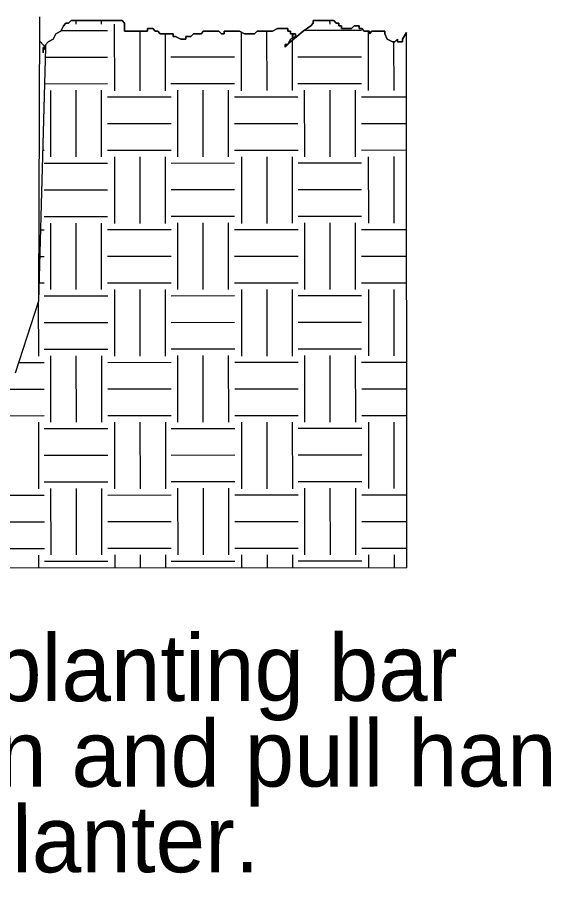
# Model space of a CAD drawing. Extents: x 816132 to 817815, y 885694 to 886789.
# Drawn here: x 816662 to 816715.4, y 886354.3 to 886442.4 of the extents above; entities that cross this region are included whole.
import ezdxf

# ---------------------------------------------------------------- set-up
doc = ezdxf.new("R2010")
doc.units = 0
doc.layers.add('Silt Fence Coir Fiber Wattle Break Detail CELL', color=7, linetype='Continuous')

msp = doc.modelspace()

# ---------------------------------------------------------------- linework, layer by layer
at = {"layer": 'Silt Fence Coir Fiber Wattle Break Detail CELL'}
for p, q in [((816664.16, 886442.456), (816664.068, 886413.823)), ((816667.818, 886442.08), (816667.818, 886441.711)), ((816670.374, 886442.082), (816670.374, 886441.713)), ((816671.7, 886441.714), (816671.705, 886435.01)), ((816693.382, 886442.1), (816693.383, 886441.731)), ((816666.366, 886441.086), (816671.014, 886441.09)), ((816674.257, 886441.006), (816674.261, 886435.012)), ((816676.814, 886440.739), (816676.818, 886435.014)), ((816684.483, 886440.913), (816684.487, 886435.02)), ((816687.039, 886441.016), (816687.044, 886435.022)), ((816689.596, 886440.749), (816689.597, 886440.3)), ((816690.831, 886441.105), (816696.579, 886441.11)), ((816697.265, 886441.024), (816697.27, 886435.03)), ((816701.141, 886387.011), (816701.103, 886440.893)), ((816664.224, 886439.97), (816664.785, 886439.382)), ((816689.596, 886440.084), (816689.6, 886435.024)), ((816699.823, 886439.949), (816699.826, 886435.032)), ((816664.785, 886439.382), (816664.068, 886413.823)), ((816664.757, 886438.404), (816671.016, 886438.408)), ((816677.407, 886438.413), (816683.798, 886438.418)), ((816690.19, 886438.423), (816696.58, 886438.428)), ((816664.682, 886435.722), (816671.018, 886435.727)), ((816677.409, 886435.732), (816683.8, 886435.736)), ((816690.191, 886435.741), (816696.582, 886435.746)), ((816665.267, 886435.051), (816665.271, 886428.347)), ((816667.822, 886435.054), (816667.828, 886428.349)), ((816670.379, 886435.056), (816670.385, 886428.352)), ((816671.019, 886434.386), (816677.41, 886434.391)), ((816678.048, 886435.062), (816678.053, 886428.357)), ((816680.605, 886435.064), (816680.61, 886428.36)), ((816683.161, 886435.066), (816683.166, 886428.362)), ((816683.801, 886434.396), (816690.193, 886434.401)), ((816690.831, 886435.072), (816690.836, 886428.368)), ((816693.387, 886435.074), (816693.392, 886428.37)), ((816695.944, 886435.075), (816695.949, 886428.372)), ((816696.583, 886434.406), (816701.108, 886434.409)), ((816683.804, 886431.714), (816690.194, 886431.719)), ((816696.585, 886431.724), (816701.11, 886431.727)), ((816664.57, 886431.699), (816664.629, 886431.699)), ((816671.021, 886431.704), (816677.412, 886431.709)), ((816664.495, 886429.017), (816664.632, 886429.018)), ((816671.023, 886429.023), (816677.414, 886429.028)), ((816671.709, 886428.353), (816671.715, 886421.649)), ((816674.266, 886428.355), (816674.271, 886421.65)), ((816676.822, 886428.357), (816676.828, 886421.652)), ((816683.805, 886429.033), (816690.196, 886429.038)), ((816684.492, 886428.363), (816684.496, 886421.659)), ((816687.048, 886428.365), (816687.053, 886421.66)), ((816689.605, 886428.367), (816689.61, 886421.663)), ((816696.588, 886429.042), (816701.111, 886429.046)), ((816697.274, 886428.373), (816697.279, 886421.668)), ((816699.831, 886428.375), (816699.836, 886421.671)), ((816664.633, 886427.724), (816671.023, 886427.729)), ((816677.415, 886427.734), (816683.806, 886427.739)), ((816690.197, 886427.743), (816696.588, 886427.749)), ((816664.634, 886425.042), (816671.026, 886425.047)), ((816677.417, 886425.052), (816683.807, 886425.057)), ((816690.199, 886425.062), (816696.59, 886425.067)), ((816664.637, 886422.36), (816671.028, 886422.365)), ((816677.418, 886422.371), (816683.81, 886422.375)), ((816690.201, 886422.38), (816696.592, 886422.385)), ((816665.276, 886421.69), (816665.281, 886414.986)), ((816667.833, 886421.693), (816667.837, 886414.988)), ((816670.389, 886421.694), (816670.394, 886414.99)), ((816678.058, 886421.701), (816678.063, 886414.996)), ((816680.614, 886421.703), (816680.619, 886414.998)), ((816683.171, 886421.705), (816683.176, 886415.001)), ((816690.84, 886421.711), (816690.845, 886415.006)), ((816693.397, 886421.713), (816693.402, 886415.009)), ((816695.953, 886421.714), (816695.958, 886415.011)), ((816664.27, 886421.019), (816664.637, 886421.019)), ((816671.029, 886421.024), (816677.419, 886421.029)), ((816683.811, 886421.035), (816690.202, 886421.04)), ((816696.593, 886421.045), (816701.117, 886421.048)), ((816664.194, 886418.338), (816664.639, 886418.338)), ((816671.03, 886418.342), (816677.421, 886418.348)), ((816683.813, 886418.353), (816690.204, 886418.358)), ((816696.595, 886418.363), (816701.119, 886418.366)), ((816664.12, 886415.656), (816664.641, 886415.656)), ((816671.032, 886415.661), (816677.423, 886415.667)), ((816671.72, 886414.991), (816671.724, 886408.288)), ((816674.276, 886414.993), (816674.281, 886408.289)), ((816676.832, 886414.996), (816676.837, 886408.291)), ((816683.815, 886415.672), (816690.206, 886415.677)), ((816684.501, 886415.001), (816684.506, 886408.298)), ((816687.058, 886415.004), (816687.062, 886408.299)), ((816689.614, 886415.006), (816689.619, 886408.301)), ((816696.597, 886415.681), (816701.121, 886415.685)), ((816697.284, 886415.012), (816697.288, 886408.307)), ((816699.84, 886415.014), (816699.845, 886408.309)), ((816664.642, 886414.362), (816671.034, 886414.368)), ((816677.424, 886414.373), (816683.815, 886414.378)), ((816690.207, 886414.382), (816696.598, 886414.387)), ((816664.068, 886413.823), (816661.727, 886406.589)), ((816664.068, 886413.823), (816661.727, 886406.589)), ((816664.051, 886413.767), (816664.055, 886408.281)), ((816664.643, 886411.68), (816671.035, 886411.686)), ((816677.426, 886411.691), (816683.818, 886411.696)), ((816690.209, 886411.701), (816696.599, 886411.706)), ((816664.646, 886408.999), (816671.037, 886409.004)), ((816677.428, 886409.009), (816683.819, 886409.014)), ((816690.21, 886409.019), (816696.602, 886409.024)), ((816665.286, 886408.329), (816665.29, 886401.625)), ((816667.842, 886408.331), (816667.847, 886401.627)), ((816670.399, 886408.333), (816670.403, 886401.629)), ((816678.067, 886408.339), (816678.073, 886401.635)), ((816680.624, 886408.342), (816680.629, 886401.637)), ((816683.18, 886408.344), (816683.186, 886401.639)), ((816690.85, 886408.35), (816690.854, 886401.645)), ((816693.406, 886408.352), (816693.411, 886401.647)), ((816695.963, 886408.353), (816695.968, 886401.65)), ((816662.072, 886407.657), (816664.647, 886407.658)), ((816671.038, 886407.663), (816677.429, 886407.668)), ((816683.82, 886407.673), (816690.212, 886407.679)), ((816696.602, 886407.684), (816701.127, 886407.687)), ((816658.257, 886404.972), (816664.649, 886404.976)), ((816671.04, 886404.981), (816677.431, 886404.986)), ((816683.822, 886404.991), (816690.213, 886404.997)), ((816696.605, 886405.002), (816701.129, 886405.005)), ((816658.259, 886402.29), (816664.651, 886402.295)), ((816671.042, 886402.3), (816677.433, 886402.305)), ((816683.824, 886402.31), (816690.215, 886402.316)), ((816696.607, 886402.32), (816701.13, 886402.324)), ((816664.06, 886401.624), (816664.064, 886394.92)), ((816664.651, 886401.001), (816671.043, 886401.006)), ((816671.729, 886401.63), (816671.734, 886394.926)), ((816674.286, 886401.632), (816674.29, 886394.928)), ((816676.842, 886401.634), (816676.847, 886394.93)), ((816677.434, 886401.011), (816683.825, 886401.017)), ((816684.511, 886401.64), (816684.516, 886394.936)), ((816687.067, 886401.642), (816687.073, 886394.938)), ((816689.624, 886401.645), (816689.629, 886394.94)), ((816690.216, 886401.021), (816696.607, 886401.026)), ((816697.293, 886401.65), (816697.298, 886394.946)), ((816699.85, 886401.653), (816699.854, 886394.948)), ((816664.654, 886398.319), (816671.045, 886398.324)), ((816677.436, 886398.33), (816683.827, 886398.335)), ((816690.218, 886398.34), (816696.609, 886398.345)), ((816664.656, 886395.637), (816671.046, 886395.643)), ((816677.438, 886395.648), (816683.829, 886395.653)), ((816690.22, 886395.658), (816696.611, 886395.663)), ((816665.295, 886394.968), (816665.3, 886388.264)), ((816667.852, 886394.97), (816667.856, 886388.266)), ((816670.408, 886394.972), (816670.413, 886388.268)), ((816678.078, 886394.978), (816678.082, 886388.274)), ((816680.634, 886394.98), (816680.639, 886388.276)), ((816683.191, 886394.982), (816683.195, 886388.278)), ((816690.859, 886394.988), (816690.865, 886388.284)), ((816693.416, 886394.99), (816693.42, 886388.286)), ((816695.972, 886394.992), (816695.977, 886388.288)), ((816658.265, 886394.292), (816664.656, 886394.297)), ((816671.048, 886394.302), (816677.438, 886394.307)), ((816683.83, 886394.312), (816690.221, 886394.317)), ((816696.612, 886394.322), (816701.136, 886394.326)), ((816658.267, 886391.611), (816664.659, 886391.615)), ((816671.049, 886391.62), (816677.44, 886391.625)), ((816683.832, 886391.63), (816690.223, 886391.635)), ((816696.614, 886391.64), (816701.138, 886391.644)), ((816658.269, 886388.929), (816664.66, 886388.934)), ((816671.051, 886388.939), (816677.443, 886388.944)), ((816683.834, 886388.949), (816690.224, 886388.954)), ((816696.616, 886388.959), (816701.14, 886388.963)), ((816664.069, 886388.263), (816664.07, 886386.982)), ((816671.739, 886388.269), (816671.739, 886386.988)), ((816674.295, 886388.271), (816674.296, 886386.99)), ((816676.852, 886388.273), (816676.852, 886386.993)), ((816684.521, 886388.279), (816684.522, 886386.998)), ((816687.078, 886388.281), (816687.078, 886387.001)), ((816689.633, 886388.283), (816689.635, 886387.003)), ((816690.226, 886387.66), (816696.617, 886387.665)), ((816697.303, 886388.289), (816697.304, 886387.009)), ((816699.859, 886388.291), (816699.86, 886387.011)), ((816625.166, 886386.952), (816701.141, 886387.011)), ((816664.661, 886387.64), (816671.052, 886387.645)), ((816677.443, 886387.65), (816683.835, 886387.654))]:
    msp.add_line(p, q, dxfattribs=at)
for points in [[(816664.224, 886439.97), (816664.271, 886439.921), (816664.785, 886439.382), (816664.529, 886439.382), (816664.529, 886439.112), (816664.529, 886438.844), (816664.529, 886439.112), (816664.785, 886439.382), (816664.785, 886439.652), (816665.042, 886439.922), (816665.555, 886440.192), (816665.811, 886440.73), (816666.324, 886441), (816666.581, 886441.54), (816666.836, 886441.808), (816667.093, 886441.809), (816667.35, 886442.079), (816667.607, 886442.079), (816667.863, 886442.079), (816668.377, 886442.08), (816668.634, 886442.08), (816669.147, 886442.081), (816669.404, 886442.08), (816669.66, 886442.081), (816669.917, 886442.081), (816670.173, 886442.082), (816670.43, 886442.082), (816671.2, 886442.083), (816671.457, 886442.082), (816671.714, 886442.082), (816671.97, 886442.083), (816672.227, 886442.083), (816672.484, 886442.083), (816672.74, 886441.813), (816672.741, 886441.274), (816672.741, 886441.005), (816672.998, 886441.005), (816673.511, 886441.006), (816674.024, 886441.006), (816674.281, 886441.006), (816674.538, 886441.006), (816674.795, 886441.007), (816675.052, 886441.007), (816675.051, 886441.276), (816675.307, 886441.277), (816675.564, 886441.277), (816675.821, 886441.007), (816676.078, 886441.007), (816676.335, 886440.739), (816676.592, 886440.739), (816676.847, 886440.739), (816677.106, 886440.74), (816677.362, 886440.739), (816677.618, 886440.74), (816677.618, 886440.47), (816677.875, 886440.47), (816678.388, 886440.202), (816678.645, 886440.202), (816678.902, 886440.202), (816678.902, 886440.47), (816679.159, 886440.47), (816679.415, 886440.471), (816679.672, 886440.741), (816679.928, 886440.742), (816680.184, 886440.742), (816680.443, 886440.742), (816680.698, 886441.011), (816681.212, 886441.012), (816681.469, 886441.012), (816681.725, 886441.012), (816681.981, 886441.012), (816682.238, 886441.012), (816682.496, 886440.743), (816682.752, 886440.744), (816682.751, 886441.013), (816683.008, 886441.013), (816683.265, 886441.014), (816683.522, 886441.014), (816683.778, 886441.013), (816684.035, 886441.014), (816684.291, 886441.014), (816684.805, 886440.745), (816685.062, 886440.746), (816685.318, 886440.745), (816685.575, 886440.746), (816685.832, 886440.746), (816686.088, 886441.015), (816686.344, 886441.016), (816686.602, 886441.016), (816686.859, 886441.016), (816687.115, 886441.016), (816687.629, 886441.017), (816688.141, 886441.286)], [(816688.141, 886441.286), (816687.629, 886441.017), (816687.115, 886441.016), (816686.859, 886441.016), (816686.602, 886441.016), (816686.344, 886441.016), (816686.088, 886441.015), (816685.832, 886440.746), (816685.575, 886440.746), (816685.318, 886440.745), (816685.062, 886440.746), (816684.805, 886440.745), (816684.291, 886441.014), (816684.035, 886441.014), (816683.778, 886441.013), (816683.522, 886441.014), (816683.265, 886441.014), (816683.008, 886441.013), (816682.751, 886441.013), (816682.752, 886440.744), (816682.496, 886440.743), (816682.238, 886441.012), (816681.981, 886441.012), (816681.725, 886441.012), (816681.469, 886441.012), (816681.212, 886441.012), (816680.698, 886441.011), (816680.443, 886440.742), (816680.184, 886440.742), (816679.928, 886440.742), (816679.672, 886440.741), (816679.415, 886440.471), (816679.159, 886440.47), (816678.902, 886440.47), (816678.902, 886440.202), (816678.645, 886440.202), (816678.388, 886440.202), (816677.875, 886440.47), (816677.618, 886440.47), (816677.618, 886440.74), (816677.362, 886440.739), (816677.106, 886440.74), (816676.847, 886440.739), (816676.592, 886440.739), (816676.335, 886440.739), (816676.078, 886441.007), (816675.821, 886441.007), (816675.564, 886441.277), (816675.307, 886441.277), (816675.051, 886441.276), (816675.052, 886441.007), (816674.795, 886441.007), (816674.538, 886441.006), (816674.281, 886441.006), (816674.024, 886441.006), (816673.511, 886441.006), (816672.998, 886441.005), (816672.741, 886441.005), (816672.741, 886441.274), (816672.74, 886441.813), (816672.484, 886442.083), (816672.227, 886442.083), (816671.97, 886442.083), (816671.714, 886442.082), (816671.457, 886442.082), (816671.2, 886442.083), (816670.43, 886442.082), (816670.173, 886442.082), (816669.917, 886442.081), (816669.66, 886442.081), (816669.404, 886442.08), (816669.147, 886442.081), (816668.634, 886442.08), (816668.377, 886442.08), (816667.863, 886442.079), (816667.607, 886442.079), (816667.35, 886442.079), (816667.093, 886441.809), (816666.836, 886441.808), (816666.581, 886441.54), (816666.324, 886441), (816665.811, 886440.73), (816665.555, 886440.192), (816665.042, 886439.922), (816664.785, 886439.652), (816664.785, 886439.382), (816664.529, 886439.112), (816664.529, 886438.844), (816664.529, 886439.112), (816664.529, 886439.382), (816664.785, 886439.382), (816664.271, 886439.921), (816664.224, 886439.97)], [(816688.141, 886441.286), (816688.655, 886441.286), (816688.912, 886441.287), (816689.168, 886441.287), (816689.169, 886441.018), (816689.425, 886441.018), (816689.425, 886440.749), (816689.425, 886441.018), (816689.425, 886440.749), (816689.682, 886440.749), (816689.682, 886440.479), (816689.682, 886440.749), (816689.94, 886440.749), (816689.94, 886440.479), (816689.426, 886440.211), (816689.169, 886439.672), (816688.913, 886439.671), (816688.913, 886439.402), (816689.426, 886439.941), (816690.708, 886441.019), (816691.478, 886441.559), (816691.735, 886441.828), (816691.734, 886442.098), (816691.991, 886442.098), (816692.505, 886442.099), (816692.76, 886442.1), (816693.018, 886442.099), (816693.275, 886442.1), (816693.531, 886442.1), (816693.787, 886442.1), (816694.045, 886441.83), (816694.301, 886441.83), (816694.302, 886441.561), (816694.559, 886441.562), (816694.559, 886441.292), (816694.815, 886441.291), (816695.072, 886441.291), (816695.585, 886441.292), (816695.841, 886441.563), (816696.099, 886441.563), (816696.356, 886441.563), (816696.356, 886441.293), (816696.612, 886441.292), (816696.869, 886441.024), (816697.125, 886441.024), (816697.383, 886441.024), (816697.383, 886440.756), (816697.639, 886441.025), (816697.896, 886441.025), (816698.151, 886441.025), (816698.41, 886441.025), (816698.665, 886441.025), (816698.922, 886441.026), (816698.923, 886440.757), (816699.18, 886440.218), (816699.693, 886439.949), (816699.95, 886439.948), (816700.206, 886440.219), (816700.206, 886439.949), (816700.463, 886439.949), (816700.719, 886439.95), (816700.719, 886440.22), (816701.103, 886440.893), (816701.103, 886440.893)], [(816701.103, 886440.893), (816701.103, 886440.893), (816700.719, 886440.22), (816700.719, 886439.95), (816700.463, 886439.949), (816700.206, 886439.949), (816700.206, 886440.219), (816699.95, 886439.948), (816699.693, 886439.949), (816699.18, 886440.218), (816698.923, 886440.757), (816698.922, 886441.026), (816698.665, 886441.025), (816698.41, 886441.025), (816698.151, 886441.025), (816697.896, 886441.025), (816697.639, 886441.025), (816697.383, 886440.756), (816697.383, 886441.024), (816697.125, 886441.024), (816696.869, 886441.024), (816696.612, 886441.292), (816696.356, 886441.293), (816696.356, 886441.563), (816696.099, 886441.563), (816695.841, 886441.563), (816695.585, 886441.292), (816695.072, 886441.291), (816694.815, 886441.291), (816694.559, 886441.292), (816694.559, 886441.562), (816694.302, 886441.561), (816694.301, 886441.83), (816694.045, 886441.83), (816693.787, 886442.1), (816693.531, 886442.1), (816693.275, 886442.1), (816693.018, 886442.099), (816692.76, 886442.1), (816692.505, 886442.099), (816691.991, 886442.098), (816691.734, 886442.098), (816691.735, 886441.828), (816691.478, 886441.559), (816690.708, 886441.019), (816689.426, 886439.941), (816688.913, 886439.402), (816688.913, 886439.671), (816689.169, 886439.672), (816689.426, 886440.211), (816689.94, 886440.479), (816689.94, 886440.749), (816689.682, 886440.749), (816689.682, 886440.479), (816689.682, 886440.749), (816689.425, 886440.749), (816689.425, 886441.018), (816689.425, 886440.749), (816689.425, 886441.018), (816689.169, 886441.018), (816689.168, 886441.287), (816688.912, 886441.287), (816688.655, 886441.286), (816688.141, 886441.286)]]:
    msp.add_lwpolyline(points, dxfattribs=at)

# ---------------------------------------------------------------- texts
for s, p in [('1. Insert planting bar ', (816624.52, 886373.514)), (' as shown and pull handle ', (816624.527, 886364.894)), (' toward planter.', (816624.533, 886356.274))]:
    msp.add_text(s, height=6.70408, rotation=0.04504, dxfattribs=at).set_placement(p)

doc.saveas('drawing.dxf')
